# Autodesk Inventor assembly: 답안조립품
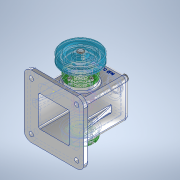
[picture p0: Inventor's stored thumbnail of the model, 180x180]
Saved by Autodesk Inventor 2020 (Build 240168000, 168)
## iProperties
Created: 2022-11
Part Number: 답안조립품
Document SubType Name: Assembly
Designer: USER
Author: USER
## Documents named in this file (16)
- C:\Users\USER\Desktop\721106V1018\답안조립품.iam
- C:\Users\USER\Desktop\721106V1018\부시.ipt
- C:\Users\USER\Desktop\721106V1018\편심축.ipt
- C:\Users\USER\Desktop\721106V1018\베어링 6201.ipt
- C:\Users\USER\Desktop\721106V1018\뒤커버.ipt
- C:\Users\USER\Desktop\721106V1018\앞커버.ipt
- C:\Users\USER\Desktop\721106V1018\볼트 M4 x 12.ipt
- C:\Users\USER\Desktop\721106V1018\링크.ipt
- C:\Users\USER\Desktop\721106V1018\슬라이드.ipt
- C:\Users\USER\Desktop\721106V1018\핀 5 x 18.ipt
- C:\Users\USER\Desktop\721106V1018\고정핀 1.2 x 10.ipt
- C:\Users\USER\Desktop\721106V1018\오일실 12 25 7.ipt
- C:\Users\USER\Desktop\721106V1018\키 4 x 4 x 15.ipt
- C:\Users\USER\Desktop\721106V1018\V벨트풀리.ipt
- C:\Users\USER\Desktop\721106V1018\멈춤나사 M3 x 8.ipt
- C:\Users\USER\Desktop\721106V1018\본체.ipt
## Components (11 placed, 4 different names)
1. ISO 4762 M4 x 12:1
2. ISO 4762 M4 x 12:2
3. ISO 4762 M4 x 12:3
4. ISO 4762 M4 x 12:4
5. ISO 4762 M4 x 12:5
6. ISO 4762 M4 x 12:6
7. ISO 4762 M4 x 12:7
8. ISO 4762 M4 x 12:8
9. 핀 5 x 18:1
10. 고정핀 1.2 x 10:1
11. V벨트풀리:1
